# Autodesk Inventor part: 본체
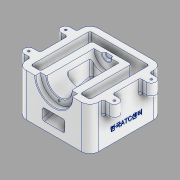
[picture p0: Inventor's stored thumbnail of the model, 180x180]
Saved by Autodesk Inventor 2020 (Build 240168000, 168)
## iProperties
Created: 2022-03
Part Number: 본체
Material: 알루미늄 6061
Document SubType Name: Modeling
Designer: Administrator
Density: 2.7 g/cm^3
Appearance: 알루미늄 - 평지
Mass: 1023.66 g
Surface Area: 844.892 cm^2
Volume: 379.135 cm^3
Author: Administrator
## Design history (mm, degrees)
sketch "스케치4"
  geometry: L1 (55, -55)-(-55, -55); L2 (-55, -55)-(-55, 55); L3 (-55, 55)-(55, 55); L4 (55, 55)-(55, -55); L5 (55, -55)-(-55, 55); L6 (-55, -55)-(55, 55); 1 further point
  constraints: 12 end point, 2 midpoint, 2 parallel, 1 horizontal, 1 perpendicular
  dimensions: "d0" = 110 distance of L2.end L3.end; "d1" = 110 distance of L1.end L2.end
extrude "돌출1" new body sketch "스케치4" distance "d2" = 65; taper "d3" = 0 deg
sketch "스케치5"
  geometry: L1 (110, 65)-(0, 65) reference; C1 r 19 at (55, 65); 1 further point
  constraints: 1 centre point, 1 midpoint
  dimensions: "d4" = 38 diameter of C1
extrude "돌출2" cut sketch "스케치5" distance "d5" = 80; taper "d6" = 0 deg
sketch "스케치6"
  geometry: L1 (110, 65)-(0, 65) reference; C1 r 28 at (55, 65); 1 further point
  constraints: 1 centre point, 1 midpoint
  dimensions: "d7" = 56 diameter of C1
extrude "돌출3" cut sketch "스케치6" distance "d8" = 8; taper "d9" = 0 deg
sketch "스케치7"
  geometry: L1 (28, -55)-(-28, -55) reference; L2 (0, -55)-(0, 55); L3 (55, 55)-(-55, 55) reference; L4 (19, 25)-(19, -47) reference; L5 (5.191, 29)-(0, 29); L6 (5.191, 29)-(7.5, 25); L7 (-19, 25)-(19, 25) reference; L8 (7.5, 25)-(0, 25); 2 further points
  constraints: 8 end point, 3 midpoint, 2 point on line, 1 perpendicular
  dimensions: "d14" = 120 deg angle of L7 L6; "d15" = 4 distance between parallel lines of L7 L5; "d85" = 15 diameter of L6.end L2
revolve "회전1" sketch "스케치7" stored, may be unused: angle "d16" = 90 deg
sketch "스케치11"
  geometry: L1 (19, 60.532)-(19, 31.425); L2 (19, 31.425)-(-55, 11.597); L3 (-55, 0)-(-55, 65) reference; L4 (19, 60.532)-(-19, 60.532); L5 (-19, 60.532)-(-19, 38.843); L6 (-19, 38.843)-(-55, 29.197); L7 (-55, 65)-(55, 65) reference; L8 (33, 65)-(33, 30); L9 (33, 30)-(-44.949, 9.114); L10 (-44.949, 9.114)-(-44.949, 0); L11 (-55, 0)-(55, 0) reference; L12 (55, 0)-(55, 65) reference; 1 further point
  constraints: 16 end point, 4 point on line, 2 vertical, 1 horizontal, 1 parallel, 1 perpendicular
  dimensions: "d20" = 17 distance between parallel lines of L2 L6; "d21" = 38 distance of L1.start L4.end; "d22" = 36 distance between parallel lines of L3 L5; "d23" = 75 deg angle of L2 L1; "d24" = 30 distance from line of L11 L8.end; "d25" = 22 distance between parallel lines of L12 L8; "d26" = 5 distance between parallel lines of L2 L9
extrude "돌출4" cut sketch "스케치11" stored distance "d27" = 34; taper "d28" = 0 deg
sketch "스케치12"
  geometry: L1 (-45, -45)-(-45, 45); L2 (-45, 45)-(45, 45); L3 (45, 45)-(45, -45); L4 (45, -45)-(30, -45); L5 (30, -45)-(30, 33); L6 (30, 33)-(-30, 33); L7 (-30, 33)-(-30, -45); L8 (-30, -45)-(-45, -45); L9 (-55, 55)-(-55, -55) reference; L10 (-55, -55)-(-28, -55) reference; L11 (28, -55)-(55, -55) reference; L12 (55, -55)-(55, 55) reference; L13 (55, 55)-(-55, 55) reference; 1 further point
  constraints: 16 end point, 6 perpendicular, 2 vertical
  dimensions: "d29" = 10 distance between parallel lines of L9 L1; "d30" = 25 distance between parallel lines of L9 L7; "d31" = 10 distance between parallel lines of L10 L8; "d32" = 10 distance between parallel lines of L11 L4; "d33" = 10 distance between parallel lines of L12 L3; "d34" = 25 distance between parallel lines of L12 L5; "d35" = 10 distance between parallel lines of L13 L2; "d36" = 22 distance between parallel lines of L6 L13
extrude "돌출5" cut sketch "스케치12" extent not by distance; stored distance "d37" = 0; taper "d38" = 0 deg
sketch "스케치13"
  geometry: L1 (33, 65)-(33, 0) reference; L2 (-45, 65)-(-45, 0) reference; L3 (-55, 11.597)-(19, 31.425) reference; L4 (33, 30)-(-45, 9.1); L5 (-45, 9.1)-(-45, 0); L6 (-55, 0)-(55, 0) reference; L7 (-55, 0)-(-55, 65) reference; L8 (-45, 0)-(33, 0); L9 (33, 0)-(33, 30); 2 further points
  constraints: 8 end point, 2 point on line, 1 collinear, 1 horizontal, 1 vertical
  dimensions: "d40" = 30 distance from line of L6 L4.start; "d41" = 10 distance between parallel lines of L7 L5; "d42" = 75 deg angle of L1 L4
extrude "돌출6" cut sketch "스케치13" stored distance "d43" = 60; taper "d44" = 0 deg
sketch "스케치14"
  geometry: L1 (-55, 55)-(-55, -55) reference; L2 (-55, 35)-(-65, 35); L3 (-65, 35)-(-65, 21); L4 (-65, 21)-(-55, 21); L5 (55, 55)-(-55, 55) reference; L6 (-65, -21)-(-55, -21); L7 (-65, -35)-(-55, -35); L8 (-55, -35)-(-55, -21); L9 (-55, 21)-(-55, 35); A1 r 7 centre (-65, -28) between (-65, -21) and (-65, -35); 3 further points
  constraints: 14 end point, 4 perpendicular, 4 point on line, 2 collinear, 2 point on circle, 2 tangent, 1 centre point, 1 horizontal, 1 midpoint, 1 vertical alignment, 3 other
  dimensions: "d45" = 14 distance between parallel lines of L4 L2; "d47" = 27 distance from line of point (-65, 28) L5; "d48" = 65 horizontal distance of point (0, 0) point (-65, 28); "d49" = 14 distance between parallel lines of L7 L6; "d50" = 56 distance of point (-65, 28) A1.centre
extrude "돌출7" join sketch "스케치14" distance "d51" = 20; taper "d52" = 0 deg
sketch "스케치15"
  geometry: L1 (-45, -45)-(-45, 45) reference; L2 (-45, 45)-(45, 45) reference; L3 (45, 45)-(45, -45) reference; L4 (45, -45)-(30, -45) reference; L5 (30, -45)-(30, 33) reference; L6 (30, 33)-(-30, 33) reference; L7 (-30, 33)-(-30, -45) reference; L8 (-30, -45)-(-45, -45) reference; L9 (-7.5, 25)-(-5.191, 29) reference; L10 (-5.191, 29)-(5.191, 29) reference; L11 (5.191, 29)-(7.5, 25) reference; L12 (7.5, 25)-(19, 25) reference; L13 (19, 25)-(19, -47) reference; L14 (19, -47)-(28, -47) reference; L15 (28, -47)-(28, -55) reference; L16 (28, -55)-(55, -55) reference; L17 (55, -55)-(55, 55) reference; L18 (55, 55)-(-55, 55) reference; L19 (-55, 55)-(-55, 35) reference; L20 (-55, 35)-(-65, 35) reference; L21 (-65, 21)-(-55, 21) reference; L22 (-55, 21)-(-55, -21) reference; L23 (-55, -21)-(-65, -21) reference; L24 (-65, -35)-(-55, -35) reference; L25 (-55, -35)-(-55, -55) reference; L26 (-55, -55)-(-28, -55) reference; L27 (-28, -55)-(-28, -47) reference; L28 (-28, -47)-(-19, -47) reference; L29 (-19, -47)-(-19, 25) reference; L30 (-19, 25)-(-7.5, 25) reference; A1 r 7 centre (-65, 28) between (-65, 35) and (-65, 21) reference; A2 r 7 centre (-65, -28) between (-65, -21) and (-65, -35) reference; 1 further point
hole "구멍1" sketch "스케치15" at (-65, 28), (-65, -28) diameter "d53" = 3.242; stored, may be unused: countersink angle "d57" = 90 deg, drill point angle "d59" = 118 deg; dims "d54" = 9, "d55" = 4, "d56" = 2, "d58" = 11
node "작업 평면1"
node "작업 평면2"
sketch "스케치16"
  geometry: L1 (0, 0)-(-65, 0) reference; L2 (0, 0)-(0, 110) reference; 2 further points
  constraints: 1 other
  dimensions: "d61" = 55 distance from line of L1 point (-20, 55); "d62" = 20 distance from line of L2 point (-20, 55)
feature "엠보싱1" sketch "스케치16" dims "d0" = 110, "d1" = 110, "d63" = 0.5, "d64" = 0
fillet "모깎기1" dims "d65" = 13
fillet "모깎기2" dims "d66" = 1
chamfer "모따기1" distance "d67" = 1; stored, may be unused: second distance "d68" = 2, angle "d69" = 45 deg
sketch "스케치17" dims "d70" = 46
  geometry: L1 (85, 65)-(25, 65) reference; 3 further points
  constraints: 1 midpoint, 1 vertical alignment, 2 other
hole "구멍2" sketch "스케치17" at (55, 42) diameter "d71" = 3.242; stored, may be unused: countersink angle "d75" = 90 deg, drill point angle "d77" = 118 deg; dims "d72" = 9, "d73" = 4, "d74" = 2, "d76" = 11
fillet "모깎기3" dims "d78" = 3
fillet "모깎기4" dims "d79" = 3
fillet "모깎기5" dims "d80" = 3
fillet "모깎기6" dims "d81" = 3
fillet "모깎기7" dims "d82" = 3
fillet "모깎기8" dims "d83" = 3
fillet "모깎기9" dims "d84" = 3
node "솔리드1"
mirror "미러1"
node "투영된 루프1"
feature "A9D066F2-1C7D-4E18-AEED-F7BC21143FA4" dims "d53" = 3.242, "d54" = 9, "d55" = 4, "d56" = 2, "d57" = 90 deg, "d58" = 11, "d59" = 118 deg
other parameters: "d60" = 63.5
